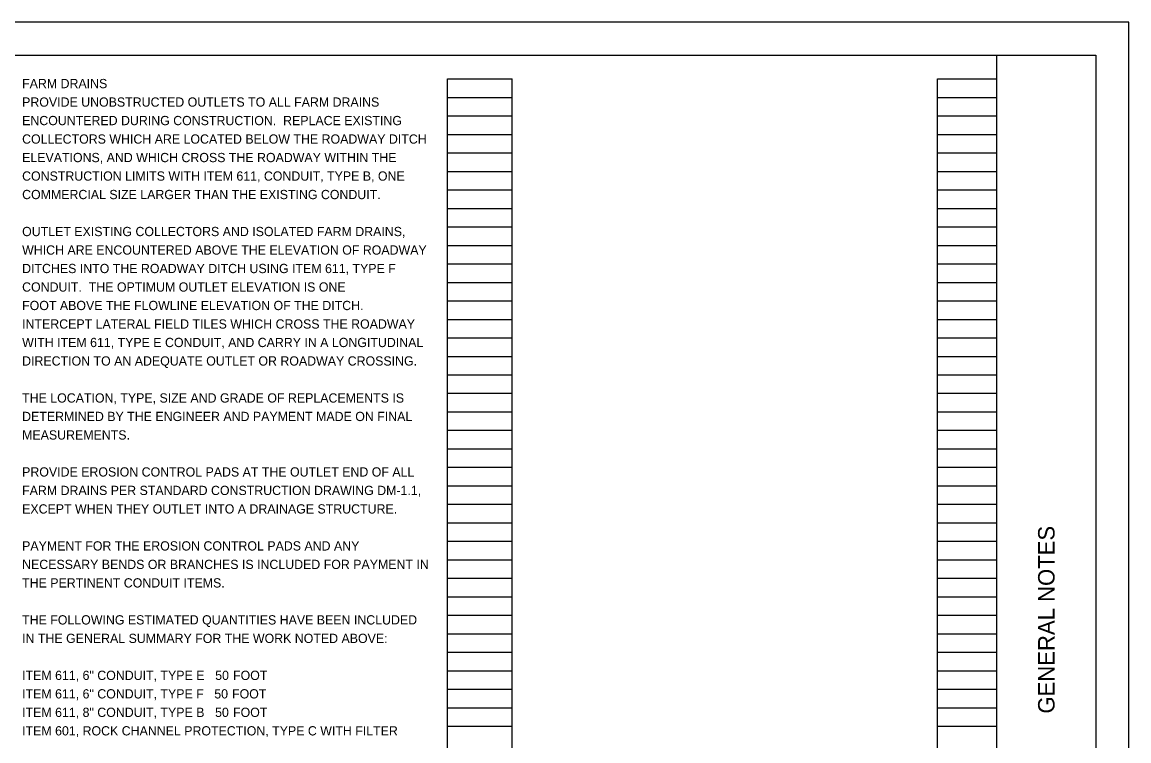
# Model space of a CAD drawing. Extents: x 0 to 34, y 0 to 22.
# Drawn here: x 17.24 to 34, y 11.12 to 22 of the extents above; entities that cross this region are included whole.
import ezdxf

# ---------------------------------------------------------------- set-up
doc = ezdxf.new("R2010")
doc.units = 0
for name, color, linetype in [('RD_P_Text', 7, 'Continuous'), ('SC_Scratch1', 7, 'Continuous'), ('SH_Border', 7, 'Continuous'), ('SH_Cut_Line', 7, 'Continuous'), ('SH_Data', 7, 'Continuous')]:
    doc.layers.add(name, color=color, linetype=linetype)

msp = doc.modelspace()

# ---------------------------------------------------------------- linework, layer by layer
at = {"layer": 'SC_Scratch1'}
for p, q in [((23.68, 0.98), (23.68, 21.14)), ((23.68, 21.14), (24.66, 21.14)), ((24.66, 0.98), (24.66, 21.14)), ((31.1, 0.98), (31.1, 21.14)), ((31.1, 21.14), (32, 21.14)), ((32, 0.98), (32, 21.14)), ((23.68, 20.86), (24.66, 20.86)), ((31.1, 20.86), (32, 20.86)), ((23.68, 20.58), (24.66, 20.58)), ((31.1, 20.58), (32, 20.58)), ((23.68, 20.3), (24.66, 20.3)), ((31.1, 20.3), (32, 20.3)), ((23.68, 20.02), (24.66, 20.02)), ((31.1, 20.02), (32, 20.02)), ((23.68, 19.74), (24.66, 19.74)), ((31.1, 19.74), (32, 19.74)), ((23.68, 19.46), (24.66, 19.46)), ((31.1, 19.46), (32, 19.46)), ((23.68, 19.18), (24.66, 19.18)), ((31.1, 19.18), (32, 19.18)), ((23.68, 18.9), (24.66, 18.9)), ((31.1, 18.9), (32, 18.9)), ((23.68, 18.62), (24.66, 18.62)), ((31.1, 18.62), (32, 18.62)), ((23.68, 18.34), (24.66, 18.34)), ((31.1, 18.34), (32, 18.34)), ((23.68, 18.06), (24.66, 18.06)), ((31.1, 18.06), (32, 18.06)), ((23.68, 17.78), (24.66, 17.78)), ((31.1, 17.78), (32, 17.78)), ((23.68, 17.5), (24.66, 17.5)), ((31.1, 17.5), (32, 17.5)), ((23.68, 17.22), (24.66, 17.22)), ((31.1, 17.22), (32, 17.22)), ((23.68, 16.94), (24.66, 16.94)), ((31.1, 16.94), (32, 16.94)), ((23.68, 16.66), (24.66, 16.66)), ((31.1, 16.66), (32, 16.66)), ((23.68, 16.38), (24.66, 16.38)), ((31.1, 16.38), (32, 16.38)), ((23.68, 16.1), (24.66, 16.1)), ((31.1, 16.1), (32, 16.1)), ((23.68, 15.82), (24.66, 15.82)), ((31.1, 15.82), (32, 15.82)), ((23.68, 15.54), (24.66, 15.54)), ((31.1, 15.54), (32, 15.54)), ((23.68, 15.26), (24.66, 15.26)), ((31.1, 15.26), (32, 15.26)), ((23.68, 14.98), (24.66, 14.98)), ((31.1, 14.98), (32, 14.98)), ((23.68, 14.7), (24.66, 14.7)), ((31.1, 14.7), (32, 14.7)), ((23.68, 14.42), (24.66, 14.42)), ((31.1, 14.42), (32, 14.42)), ((23.68, 14.14), (24.66, 14.14)), ((31.1, 14.14), (32, 14.14)), ((23.68, 13.86), (24.66, 13.86)), ((31.1, 13.86), (32, 13.86)), ((23.68, 13.58), (24.66, 13.58)), ((31.1, 13.58), (32, 13.58)), ((23.68, 13.3), (24.66, 13.3)), ((31.1, 13.3), (32, 13.3)), ((23.68, 13.02), (24.66, 13.02)), ((31.1, 13.02), (32, 13.02)), ((23.68, 12.74), (24.66, 12.74)), ((31.1, 12.74), (32, 12.74)), ((23.68, 12.46), (24.66, 12.46)), ((31.1, 12.46), (32, 12.46)), ((23.68, 12.18), (24.66, 12.18)), ((31.1, 12.18), (32, 12.18)), ((23.68, 11.9), (24.66, 11.9)), ((31.1, 11.9), (32, 11.9)), ((23.68, 11.62), (24.66, 11.62)), ((31.1, 11.62), (32, 11.62)), ((23.68, 11.34), (24.66, 11.34)), ((31.1, 11.34), (32, 11.34))]:
    msp.add_line(p, q, dxfattribs=at)
at = {"layer": 'SH_Border'}
msp.add_line((32, 0.5), (32, 21.5), dxfattribs=at)
msp.add_lwpolyline([(1.5, 21.5), (33.5, 21.5), (33.5, 0.5), (1.5, 0.5)], close=True, dxfattribs=at)
at = {"layer": 'SH_Cut_Line'}
msp.add_lwpolyline([(0, 0), (34, 0), (34, 22), (0, 22)], close=True, dxfattribs=at)

# ---------------------------------------------------------------- texts
at = {"layer": 'RD_P_Text'}
for s, p in [('FARM DRAINS', (17.24, 21)), ('PROVIDE UNOBSTRUCTED OUTLETS TO ALL FARM DRAINS ', (17.24, 20.72)), ('ENCOUNTERED DURING CONSTRUCTION.  REPLACE EXISTING ', (17.24, 20.44)), ('COLLECTORS WHICH ARE LOCATED BELOW THE ROADWAY DITCH ', (17.24, 20.16)), ('ELEVATIONS, AND WHICH CROSS THE ROADWAY WITHIN THE', (17.24, 19.88)), ('CONSTRUCTION LIMITS WITH ITEM 611, CONDUIT, TYPE B, ONE ', (17.24, 19.6)), ('COMMERCIAL SIZE LARGER THAN THE EXISTING CONDUIT.', (17.24, 19.32)), ('OUTLET EXISTING COLLECTORS AND ISOLATED FARM DRAINS, ', (17.24, 18.76)), ('WHICH ARE ENCOUNTERED ABOVE THE ELEVATION OF ROADWAY ', (17.24, 18.48)), ('DITCHES INTO THE ROADWAY DITCH USING ITEM 611, TYPE F ', (17.24, 18.2)), ('CONDUIT.  THE OPTIMUM OUTLET ELEVATION IS ONE', (17.24, 17.92)), ('FOOT ABOVE THE FLOWLINE ELEVATION OF THE DITCH.  ', (17.24, 17.64)), ('INTERCEPT LATERAL FIELD TILES WHICH CROSS THE ROADWAY ', (17.24, 17.36)), ('WITH ITEM 611, TYPE E CONDUIT, AND CARRY IN A LONGITUDINAL ', (17.24, 17.08)), ('DIRECTION TO AN ADEQUATE OUTLET OR ROADWAY CROSSING.', (17.24, 16.8)), ('THE LOCATION, TYPE, SIZE AND GRADE OF REPLACEMENTS IS ', (17.24, 16.24)), ('DETERMINED BY THE ENGINEER AND PAYMENT MADE ON FINAL ', (17.24, 15.96)), ('MEASUREMENTS.', (17.24, 15.68)), ('PROVIDE EROSION CONTROL PADS AT THE OUTLET END OF ALL ', (17.24, 15.12)), ('FARM DRAINS PER STANDARD CONSTRUCTION DRAWING DM-1.1, ', (17.24, 14.84)), ('EXCEPT WHEN THEY OUTLET INTO A DRAINAGE STRUCTURE.', (17.24, 14.56)), ('PAYMENT FOR THE EROSION CONTROL PADS AND ANY ', (17.24, 14)), ('NECESSARY BENDS OR BRANCHES IS INCLUDED FOR PAYMENT IN ', (17.24, 13.72)), ('THE PERTINENT CONDUIT ITEMS.', (17.24, 13.44)), ('THE FOLLOWING ESTIMATED QUANTITIES HAVE BEEN INCLUDED ', (17.24, 12.88)), ('IN THE GENERAL SUMMARY FOR THE WORK NOTED ABOVE:', (17.24, 12.6)), ('ITEM 611, 6" CONDUIT, TYPE E ', (17.24, 12.04)), ('50', (20.164, 12.04)), (' FOOT', (20.382, 12.04)), ('ITEM 611, 6" CONDUIT, TYPE F ', (17.24, 11.76)), ('50', (20.15, 11.76)), (' FOOT', (20.367, 11.76)), ('ITEM 611, 8" CONDUIT, TYPE B', (17.24, 11.48)), (' 50', (20.11, 11.48)), (' FOOT', (20.382, 11.48)), ('ITEM 601, ROCK CHANNEL PROTECTION, TYPE C WITH FILTER', (17.24, 11.2))]:
    msp.add_text(s, height=0.14, dxfattribs=at).set_placement(p)
at = {"layer": 'SH_Data'}
msp.add_text('GENERAL NOTES', height=0.25, rotation=90, dxfattribs=at).set_placement((32.875, 11.531))

doc.saveas('drawing.dxf')
